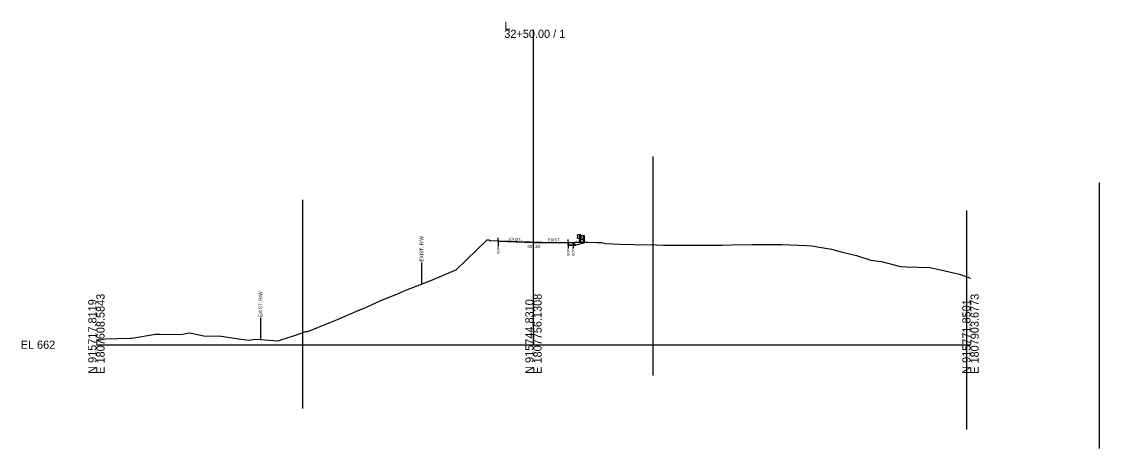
# Model space of a CAD drawing. Extents: x -26 to 1352, y -510 to 9596.
# Drawn here: x 974.3 to 1344.3, y 8464.4 to 8610.9 of the extents above; entities that cross this region are included whole.
import ezdxf

# ---------------------------------------------------------------- set-up
doc = ezdxf.new("R2010")
doc.units = 0
for name, color, linetype in [('Exist Cross Section Cell', 7, 'Continuous'), ('Exist XS Center Line Elevation Label', 7, 'Continuous'), ('Exist XS Ground Line', 7, 'Continuous'), ('Old_Level_10', 7, 'Continuous'), ('Prop XS Earthwork Shape', 7, 'Continuous'), ('Prop XS EOT Tick Mark', 7, 'Continuous'), ('Prop XS Exc Vertical Line 1', 7, 'Continuous'), ('Prop XS Exc Vertical Line 2', 7, 'Continuous'), ('Prop XS Exc Vertical Line 3', 7, 'Continuous'), ('Prop XS Exc Vertical Line 4', 7, 'Continuous'), ('Prop XS Finish Grade', 7, 'Continuous'), ('Prop XS Finish Grade Paved Shoulder', 7, 'Continuous'), ('Prop XS Finish Grade Pavement', 7, 'Continuous'), ('Prop XS Guardrail', 7, 'Continuous'), ('Prop XS Pvmt Edge Slope', 7, 'Continuous'), ('Prop XS SE Text', 7, 'Continuous'), ('Prop XS Subgrade Earthwork', 7, 'Continuous'), ('Scratch_Level_6', 7, 'Continuous')]:
    doc.layers.add(name, color=color, linetype=linetype)

msp = doc.modelspace()

# ---------------------------------------------------------------- linework, layer by layer
at = {"layer": 'Exist Cross Section Cell'}
for p, q in [((1150, 8500), (1150, 8608.14)), ((1000, 8500), (1150, 8500)), ((1150, 8500), (1300, 8500))]:
    msp.add_line(p, q, dxfattribs=at)
at = {"layer": 'Exist XS Ground Line'}
msp.add_lwpolyline([(1000, 8501.63), (1001.44, 8501.68), (1003.1, 8501.96), (1011.61, 8502.19), (1011.69, 8502.19), (1012.15, 8502.27), (1020.28, 8503.56), (1021.77, 8503.6), (1028.87, 8503.52), (1031.94, 8504.02), (1037.47, 8502.93), (1042.1, 8503.1), (1048.82, 8501.96), (1052.27, 8501.55), (1054.65, 8501.91), (1062.44, 8501.32), (1063.25, 8501.62), (1067.66, 8503.07), (1071.84, 8504.56), (1072.6, 8504.54), (1080.43, 8507.76), (1082.77, 8508.6), (1089.02, 8511.43), (1092.94, 8513.02), (1097.62, 8515.17), (1103.1, 8517.3), (1106.21, 8518.72), (1113.27, 8521.46), (1114.8, 8522.04), (1123.18, 8525.62), (1123.4, 8525.71), (1123.43, 8525.73), (1134.12, 8535.97), (1134.39, 8536.05), (1134.7, 8536.04), (1135.01, 8535.73), (1135.39, 8535.72), (1137.89, 8535.64), (1139.31, 8535.59), (1139.46, 8535.58), (1141.53, 8535.49), (1141.99, 8535.48), (1142.66, 8535.45), (1144.54, 8535.4), (1145.83, 8535.36), (1147.08, 8535.33), (1148.88, 8535.27), (1149.62, 8535.24), (1150, 8535.23), (1150.08, 8535.22), (1150.34, 8535.21), (1151.73, 8535.18), (1152.15, 8535.17), (1152.93, 8535.15), (1154.42, 8535.12), (1154.7, 8535.12), (1156.58, 8535.12), (1157.24, 8535.11), (1158.21, 8535.1), (1159.79, 8535.08), (1161.89, 8535.06), (1161.95, 8535.06), (1161.95, 8535.06), (1162.11, 8535.06), (1163.37, 8535.04), (1163.65, 8535.04), (1164.17, 8535.16), (1164.62, 8535.25), (1164.83, 8535.31), (1171.72, 8535.08), (1173.48, 8535.03), (1174.8, 8534.74), (1179.56, 8534.56), (1184.43, 8534.41), (1192.14, 8534.27), (1194.6, 8534.19), (1200.73, 8534.13), (1204.76, 8534.13), (1209.32, 8534.16), (1214.93, 8534.2), (1217.92, 8534.31), (1225.1, 8534.4), (1226.51, 8534.42), (1234.21, 8534.44), (1235.1, 8534.44), (1235.26, 8534.42), (1243.69, 8534.01), (1245.43, 8533.89), (1252.29, 8532.83), (1255.6, 8531.9), (1260.88, 8530.64), (1265.76, 8528.97), (1269.47, 8528.52), (1275.93, 8526.86), (1278.06, 8526.71), (1286.1, 8526.46), (1286.66, 8526.39), (1289.73, 8525.68), (1295.25, 8524.44), (1296.26, 8524.19), (1300, 8522.87)], dxfattribs=at)
at = {"layer": 'Old_Level_10'}
for p, q in [((1137.89, 8535.76), (1137.89, 8533.71)), ((1161.95, 8535.06), (1161.95, 8533.01)), ((1163.65, 8535.04), (1163.65, 8532.99)), ((1111.58, 8528.21), (1111.58, 8520.8)), ((1056.31, 8509.18), (1056.31, 8501.78))]:
    msp.add_line(p, q, dxfattribs=at)
at = {"layer": 'Prop XS Earthwork Shape'}
for points in [[(1163.37, 8535.04), (1163.65, 8535.04), (1164.17, 8535.16), (1164.62, 8535.25), (1164.83, 8535.31), (1168.45, 8535.19), (1164.55, 8534.14), (1161.95, 8534.14), (1161.95, 8534.93), (1150, 8535.1), (1137.89, 8535.51), (1137.89, 8535.64), (1139.31, 8535.59), (1139.46, 8535.58), (1141.53, 8535.49), (1141.99, 8535.48), (1142.66, 8535.45), (1144.54, 8535.4), (1145.83, 8535.36), (1147.08, 8535.33), (1148.88, 8535.27), (1149.62, 8535.24), (1150, 8535.23), (1150.08, 8535.22), (1150.34, 8535.21), (1151.73, 8535.18), (1152.15, 8535.17), (1152.93, 8535.15), (1154.42, 8535.12), (1154.7, 8535.12), (1156.58, 8535.12), (1157.24, 8535.11), (1158.21, 8535.1), (1159.79, 8535.08), (1161.89, 8535.06), (1161.95, 8535.06), (1162.11, 8535.06)], [(1162.11, 8535.06), (1163.37, 8535.04), (1163.65, 8535.04), (1164.17, 8535.16), (1164.62, 8535.25), (1164.83, 8535.31), (1168.45, 8535.19), (1164.55, 8534.14), (1161.95, 8534.14), (1161.95, 8534.93), (1150, 8535.1), (1137.89, 8535.51), (1137.89, 8535.64), (1139.31, 8535.59), (1139.46, 8535.58), (1141.53, 8535.49), (1141.99, 8535.48), (1142.66, 8535.45), (1144.54, 8535.4), (1145.83, 8535.36), (1147.08, 8535.33), (1148.88, 8535.27), (1149.62, 8535.24), (1150, 8535.23), (1150.08, 8535.22), (1150.34, 8535.21), (1151.73, 8535.18), (1152.15, 8535.17), (1152.93, 8535.15), (1154.42, 8535.12), (1154.7, 8535.12), (1156.58, 8535.12), (1157.24, 8535.11), (1158.21, 8535.1), (1159.79, 8535.08), (1161.89, 8535.06), (1161.95, 8535.06)], [(1162.11, 8535.06), (1163.37, 8535.04), (1163.65, 8535.04), (1164.17, 8535.16), (1164.62, 8535.25), (1164.83, 8535.31), (1168.45, 8535.19), (1164.55, 8534.14), (1161.95, 8534.14), (1161.95, 8534.93), (1150, 8535.1), (1137.89, 8535.51), (1137.89, 8535.64), (1139.31, 8535.59), (1139.46, 8535.58), (1141.53, 8535.49), (1141.99, 8535.48), (1142.66, 8535.45), (1144.54, 8535.4), (1145.83, 8535.36), (1147.08, 8535.33), (1148.88, 8535.27), (1149.62, 8535.24), (1150, 8535.23), (1150.08, 8535.22), (1150.34, 8535.21), (1151.73, 8535.18), (1152.15, 8535.17), (1152.93, 8535.15), (1154.42, 8535.12), (1154.7, 8535.12), (1156.58, 8535.12), (1157.24, 8535.11), (1158.21, 8535.1), (1159.79, 8535.08), (1161.89, 8535.06), (1161.95, 8535.06)]]:
    msp.add_lwpolyline(points, close=True, dxfattribs=at)
at = {"layer": 'Prop XS EOT Tick Mark'}
for p, q in [((1137.89, 8535.64), (1137.89, 8536.64)), ((1161.95, 8535.06), (1161.95, 8536.06))]:
    msp.add_line(p, q, dxfattribs=at)
at = {"layer": 'Prop XS Exc Vertical Line 1'}
msp.add_line((1070.86, 8478.06), (1070.86, 8549.71), dxfattribs=at)
at = {"layer": 'Prop XS Exc Vertical Line 2'}
msp.add_line((1191.07, 8489.42), (1191.07, 8564.66), dxfattribs=at)
at = {"layer": 'Prop XS Exc Vertical Line 3'}
msp.add_line((1298.78, 8470.89), (1298.78, 8546.13), dxfattribs=at)
at = {"layer": 'Prop XS Exc Vertical Line 4'}
msp.add_line((1344.26, 8464.38), (1344.26, 8555.58), dxfattribs=at)
at = {"layer": 'Prop XS Finish Grade'}
msp.add_line((1163.65, 8535.04), (1168.45, 8535.19), dxfattribs=at)
at = {"layer": 'Prop XS Finish Grade Paved Shoulder'}
msp.add_line((1161.95, 8535.06), (1163.65, 8535.06), dxfattribs=at)
at = {"layer": 'Prop XS Finish Grade Pavement'}
for p, q in [((1137.89, 8535.64), (1150, 8535.23)), ((1150, 8535.23), (1161.95, 8535.06))]:
    msp.add_line(p, q, dxfattribs=at)
at = {"layer": 'Prop XS Guardrail'}
for p, q in [((1166.24, 8537.17), (1166.21, 8537.11)), ((1166.21, 8537.11), (1166.24, 8537.05)), ((1166.24, 8536.55), (1166.21, 8536.49)), ((1166.21, 8536.49), (1166.24, 8536.43)), ((1166.53, 8537.37), (1166.24, 8537.17)), ((1166.24, 8537.05), (1166.53, 8536.85)), ((1166.53, 8536.75), (1166.24, 8536.55)), ((1166.24, 8536.43), (1166.53, 8536.23)), ((1167.03, 8537.37), (1166.53, 8537.37)), ((1166.53, 8536.85), (1166.53, 8536.75)), ((1166.53, 8536.23), (1167.03, 8536.23)), ((1167.53, 8537.37), (1167.03, 8537.37)), ((1167.03, 8537.37), (1167.03, 8534.87)), ((1167.53, 8534.87), (1167.53, 8537.37))]:
    msp.add_line(p, q, dxfattribs=at)
at = {"layer": 'Prop XS Pvmt Edge Slope'}
msp.add_line((1163.65, 8535.04), (1164.55, 8534.14), dxfattribs=at)
at = {"layer": 'Prop XS Subgrade Earthwork'}
for p, q in [((1137.89, 8535.64), (1137.89, 8535.51)), ((1137.89, 8535.51), (1150, 8535.1)), ((1150, 8535.1), (1161.95, 8534.93)), ((1161.95, 8534.93), (1161.95, 8534.14)), ((1168.45, 8535.19), (1164.55, 8534.14)), ((1161.95, 8534.14), (1164.55, 8534.14))]:
    msp.add_line(p, q, dxfattribs=at)
at = {"layer": 'Scratch_Level_6'}
for p, q in [((1165, 8537.5), (1164.97, 8537.44)), ((1164.97, 8537.44), (1165, 8537.38)), ((1165, 8536.89), (1164.97, 8536.83)), ((1164.97, 8536.83), (1165, 8536.77)), ((1165.29, 8537.7), (1165, 8537.5)), ((1165, 8537.38), (1165.29, 8537.18)), ((1165.29, 8537.09), (1165, 8536.89)), ((1165, 8536.77), (1165.29, 8536.57)), ((1165.79, 8537.7), (1165.29, 8537.7)), ((1165.29, 8537.18), (1165.29, 8537.09)), ((1165.29, 8536.57), (1165.79, 8536.57)), ((1166.29, 8537.7), (1165.79, 8537.7)), ((1165.79, 8537.7), (1165.79, 8535.2)), ((1166.29, 8535.2), (1166.29, 8537.7))]:
    msp.add_line(p, q, dxfattribs=at)

# ---------------------------------------------------------------- texts
at = {"layer": 'Exist Cross Section Cell'}
for s, p in [('L', (1140, 8608.14)), ('32+50.00 / 1', (1140, 8605.34)), ('EL 662', (974, 8498.6))]:
    msp.add_text(s, height=2.8, dxfattribs=at).set_placement(p)
for s, p in [('E 1807608.5843', (1002.8, 8490)), ('E 1807756.1308', (1152.8, 8490)), ('E 1807903.6773', (1302.8, 8490)), ('N 915717.8119', (1000, 8490)), ('N 915744.8310', (1150, 8490)), ('N 915771.8501', (1300, 8490))]:
    msp.add_text(s, height=2.8, rotation=90, dxfattribs=at).set_placement(p)
at = {"layer": 'Exist XS Center Line Elevation Label'}
msp.add_text('697.23', height=1, dxfattribs=at).set_placement((1147.95, 8533.23))
at = {"layer": 'Old_Level_10'}
for s, height, p in [('EXIST. R/W', 1.181, (1112.17, 8528.51)), ('EOP', 0.787, (1138.28, 8531.31)), ('EOP', 0.787, (1162.34, 8530.61)), ('EOP', 0.787, (1164.05, 8530.59)), ('EXIST. R/W', 1.181, (1056.9, 8509.49))]:
    msp.add_text(s, height=height, rotation=90, dxfattribs=at).set_placement(p)
at = {"layer": 'Prop XS SE Text'}
for rotation, p in [(358.8542, (1141.66, 8535.73)), (360, (1154.99, 8535.47))]:
    msp.add_text('EXIST.', height=1, rotation=rotation, dxfattribs=at).set_placement(p)

doc.saveas('drawing.dxf')
